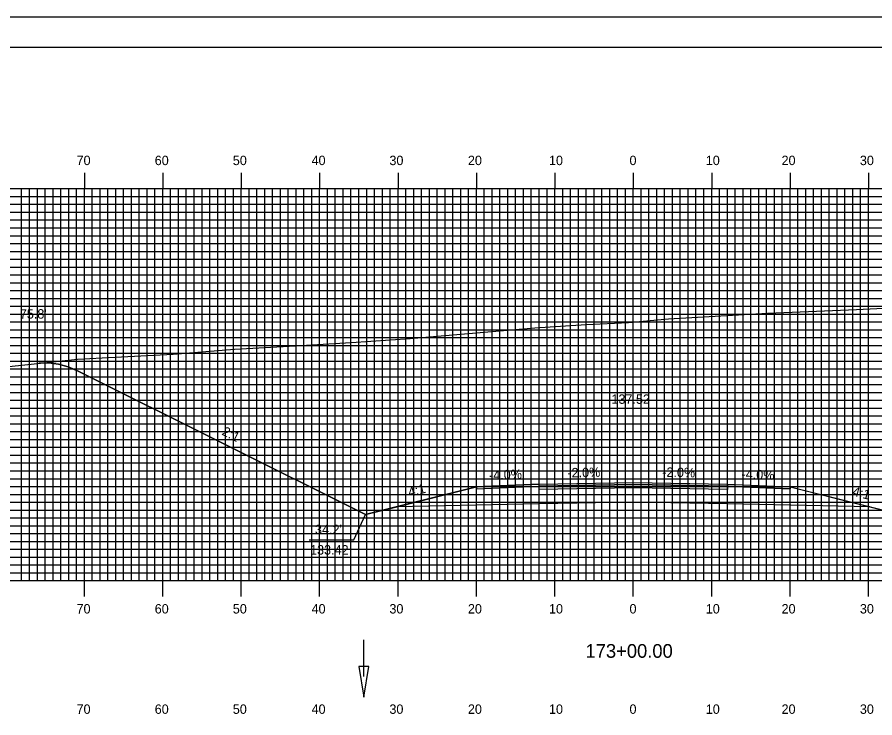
# Model space of a CAD drawing. Extents: x 1783041 to 1783384, y 442591 to 442811.
# Drawn here: x 1783127.9 to 1783237.3, y 442721.2 to 442810.5 of the extents above; entities that cross this region are included whole.
import ezdxf

# ---------------------------------------------------------------- set-up
doc = ezdxf.new("R2010")
doc.units = 0
for name, color, linetype in [('ANNOTATION', 7, 'Continuous'), ('BORDER', 7, 'Continuous'), ('D_Drainage_Ditch_Line', 7, 'Continuous'), ('D_Roadway_Centerline', 7, 'Continuous'), ('D_Roadway_Centerline_Text', 7, 'Continuous'), ('D_Roadway_Edge_Shoulder', 7, 'Continuous'), ('D_Roadway_Edge_TW', 7, 'Continuous'), ('D_Roadway_Pavement', 7, 'Continuous'), ('D_Roadway_SlopeLines', 7, 'Continuous'), ('D_Roadway_SubGrade', 7, 'Continuous'), ('D_Text_Standard', 7, 'Continuous'), ('H_V ANNOTATION', 7, 'Continuous'), ('MAJOR', 7, 'Continuous'), ('MINOR', 7, 'Continuous'), ('PLOT BOUNDARY', 7, 'Continuous'), ('S_Roadway_Centerline', 7, 'Continuous')]:
    doc.layers.add(name, color=color, linetype=linetype)

msp = doc.modelspace()

# ---------------------------------------------------------------- linework, layer by layer
at = {"layer": 'ANNOTATION'}
msp.add_lwpolyline([(1783165.13, 442743.86), (1783170.83, 442743.86), (1783172.29, 442747.09)], dxfattribs=at)
at = {"layer": 'BORDER'}
msp.add_lwpolyline([(1783056.86, 442596.67), (1783376.86, 442596.67), (1783376.86, 442806.67), (1783056.86, 442806.67)], close=True, dxfattribs=at)
at = {"layer": 'D_Drainage_Ditch_Line'}
msp.add_line((1783172.09, 442726.42), (1783172.09, 442731.12), dxfattribs=at)
msp.add_lwpolyline([(1783172.75, 442727.73), (1783171.44, 442727.73), (1783172.09, 442723.8)], close=True, dxfattribs=at)
at = {"layer": 'D_Roadway_Centerline'}
msp.add_lwpolyline([(1783130.65, 442766.39), (1783131.9, 442766.43), (1783133.15, 442766.28), (1783134.4, 442765.93), (1783135.65, 442765.4), (1783172.29, 442747.09), (1783176.29, 442748.09), (1783186.46, 442750.63), (1783194.46, 442750.95), (1783206.46, 442751.19), (1783218.46, 442750.95), (1783226.46, 442750.63), (1783236.63, 442748.09), (1783243.2, 442746.45), (1783302.51, 442776.1), (1783303.76, 442776.66), (1783305.01, 442777.08), (1783306.26, 442777.35), (1783307.51, 442777.49)], dxfattribs=at)
at = {"layer": 'D_Roadway_Edge_Shoulder'}
for points in [[(1783194.46, 442750.95), (1783186.46, 442750.63), (1783186.46, 442750.38), (1783194.46, 442750.7)], [(1783218.46, 442750.95), (1783226.46, 442750.63), (1783226.46, 442750.38), (1783218.46, 442750.7)]]:
    msp.add_lwpolyline(points, close=True, dxfattribs=at)
at = {"layer": 'D_Roadway_Edge_TW'}
msp.add_lwpolyline([(1783194.46, 442750.7), (1783194.46, 442750.95), (1783206.46, 442751.19), (1783218.46, 442750.95), (1783218.46, 442750.7), (1783206.46, 442750.94)], close=True, dxfattribs=at)
at = {"layer": 'D_Roadway_Pavement'}
msp.add_lwpolyline([(1783194.46, 442750.28), (1783194.46, 442750.7), (1783206.46, 442750.94), (1783218.46, 442750.7), (1783218.46, 442750.28), (1783206.46, 442750.52)], close=True, dxfattribs=at)
at = {"layer": 'D_Roadway_SlopeLines'}
for points in [[(1783172.29, 442747.09), (1783135.65, 442765.4), (1783134.4, 442765.93), (1783133.15, 442766.28), (1783131.9, 442766.43), (1783130.65, 442766.39)], [(1783186.46, 442750.63), (1783172.29, 442747.09)], [(1783226.46, 442750.63), (1783243.2, 442746.45)]]:
    msp.add_lwpolyline(points, dxfattribs=at)
at = {"layer": 'D_Roadway_SubGrade'}
msp.add_lwpolyline([(1783194.46, 442748.45), (1783176.29, 442748.09), (1783186.46, 442750.63), (1783186.46, 442750.38), (1783194.46, 442750.7), (1783206.46, 442750.94), (1783218.46, 442750.7), (1783226.46, 442750.38), (1783226.46, 442750.63), (1783236.63, 442748.09), (1783218.46, 442748.45), (1783206.46, 442748.69)], close=True, dxfattribs=at)
at = {"layer": 'MAJOR'}
for p, q in [((1783136.46, 442790.67), (1783136.46, 442788.67)), ((1783146.46, 442790.67), (1783146.46, 442788.67)), ((1783156.46, 442790.67), (1783156.46, 442788.67)), ((1783166.46, 442790.67), (1783166.46, 442788.67)), ((1783176.46, 442790.67), (1783176.46, 442788.67)), ((1783186.46, 442790.67), (1783186.46, 442788.67)), ((1783196.46, 442790.67), (1783196.46, 442788.67)), ((1783206.46, 442790.67), (1783206.46, 442788.67)), ((1783216.46, 442790.67), (1783216.46, 442788.67)), ((1783226.46, 442790.67), (1783226.46, 442788.67)), ((1783236.46, 442790.67), (1783236.46, 442788.67)), ((1783066.46, 442788.67), (1783346.46, 442788.67)), ((1783066.46, 442788.67), (1783346.46, 442788.67)), ((1783136.46, 442738.67), (1783136.46, 442788.67)), ((1783146.46, 442738.67), (1783146.46, 442788.67)), ((1783156.46, 442738.67), (1783156.46, 442788.67)), ((1783166.46, 442738.67), (1783166.46, 442788.67)), ((1783176.46, 442738.67), (1783176.46, 442788.67)), ((1783186.46, 442738.67), (1783186.46, 442788.67)), ((1783196.46, 442738.67), (1783196.46, 442788.67)), ((1783206.46, 442738.67), (1783206.46, 442788.67)), ((1783216.46, 442738.67), (1783216.46, 442788.67)), ((1783226.46, 442738.67), (1783226.46, 442788.67)), ((1783236.46, 442738.67), (1783236.46, 442788.67)), ((1783066.46, 442783.67), (1783346.46, 442783.67)), ((1783066.46, 442778.67), (1783346.46, 442778.67)), ((1783066.46, 442773.67), (1783346.46, 442773.67)), ((1783066.46, 442768.67), (1783346.46, 442768.67)), ((1783066.46, 442763.67), (1783346.46, 442763.67)), ((1783066.46, 442758.67), (1783346.46, 442758.67)), ((1783066.46, 442753.67), (1783346.46, 442753.67)), ((1783066.46, 442748.67), (1783346.46, 442748.67)), ((1783066.46, 442743.67), (1783346.46, 442743.67)), ((1783066.46, 442738.67), (1783346.46, 442738.67)), ((1783066.46, 442738.67), (1783346.46, 442738.67)), ((1783136.46, 442736.66), (1783136.46, 442738.67)), ((1783146.46, 442736.66), (1783146.46, 442738.67)), ((1783156.46, 442736.66), (1783156.46, 442738.67)), ((1783166.46, 442736.66), (1783166.46, 442738.67)), ((1783176.46, 442736.66), (1783176.46, 442738.67)), ((1783186.46, 442736.66), (1783186.46, 442738.67)), ((1783196.46, 442736.66), (1783196.46, 442738.67)), ((1783206.46, 442736.66), (1783206.46, 442738.67)), ((1783216.46, 442736.66), (1783216.46, 442738.67)), ((1783226.46, 442736.66), (1783226.46, 442738.67)), ((1783236.46, 442736.66), (1783236.46, 442738.67))]:
    msp.add_line(p, q, dxfattribs=at)
at = {"layer": 'MINOR'}
for p, q in [((1783128.46, 442738.67), (1783128.46, 442788.67)), ((1783129.46, 442738.67), (1783129.46, 442788.67)), ((1783130.46, 442738.67), (1783130.46, 442788.67)), ((1783131.46, 442738.67), (1783131.46, 442788.67)), ((1783132.46, 442738.67), (1783132.46, 442788.67)), ((1783133.46, 442738.67), (1783133.46, 442788.67)), ((1783134.46, 442738.67), (1783134.46, 442788.67)), ((1783135.46, 442738.67), (1783135.46, 442788.67)), ((1783137.46, 442738.67), (1783137.46, 442788.67)), ((1783138.46, 442738.67), (1783138.46, 442788.67)), ((1783139.46, 442738.67), (1783139.46, 442788.67)), ((1783140.46, 442738.67), (1783140.46, 442788.67)), ((1783141.46, 442738.67), (1783141.46, 442788.67)), ((1783142.46, 442738.67), (1783142.46, 442788.67)), ((1783143.46, 442738.67), (1783143.46, 442788.67)), ((1783144.46, 442738.67), (1783144.46, 442788.67)), ((1783145.46, 442738.67), (1783145.46, 442788.67)), ((1783147.46, 442738.67), (1783147.46, 442788.67)), ((1783148.46, 442738.67), (1783148.46, 442788.67)), ((1783149.46, 442738.67), (1783149.46, 442788.67)), ((1783150.46, 442738.67), (1783150.46, 442788.67)), ((1783151.46, 442738.67), (1783151.46, 442788.67)), ((1783152.46, 442738.67), (1783152.46, 442788.67)), ((1783153.46, 442738.67), (1783153.46, 442788.67)), ((1783154.46, 442738.67), (1783154.46, 442788.67)), ((1783155.46, 442738.67), (1783155.46, 442788.67)), ((1783157.46, 442738.67), (1783157.46, 442788.67)), ((1783158.46, 442738.67), (1783158.46, 442788.67)), ((1783159.46, 442738.67), (1783159.46, 442788.67)), ((1783160.46, 442738.67), (1783160.46, 442788.67)), ((1783161.46, 442738.67), (1783161.46, 442788.67)), ((1783162.46, 442738.67), (1783162.46, 442788.67)), ((1783163.46, 442738.67), (1783163.46, 442788.67)), ((1783164.46, 442738.67), (1783164.46, 442788.67)), ((1783165.46, 442738.67), (1783165.46, 442788.67)), ((1783167.46, 442738.67), (1783167.46, 442788.67)), ((1783168.46, 442738.67), (1783168.46, 442788.67)), ((1783169.46, 442738.67), (1783169.46, 442788.67)), ((1783170.46, 442738.67), (1783170.46, 442788.67)), ((1783171.46, 442738.67), (1783171.46, 442788.67)), ((1783172.46, 442738.67), (1783172.46, 442788.67)), ((1783173.46, 442738.67), (1783173.46, 442788.67)), ((1783174.46, 442738.67), (1783174.46, 442788.67)), ((1783175.46, 442738.67), (1783175.46, 442788.67)), ((1783177.46, 442738.67), (1783177.46, 442788.67)), ((1783178.46, 442738.67), (1783178.46, 442788.67)), ((1783179.46, 442738.67), (1783179.46, 442788.67)), ((1783180.46, 442738.67), (1783180.46, 442788.67)), ((1783181.46, 442738.67), (1783181.46, 442788.67)), ((1783182.46, 442738.67), (1783182.46, 442788.67)), ((1783183.46, 442738.67), (1783183.46, 442788.67)), ((1783184.46, 442738.67), (1783184.46, 442788.67)), ((1783185.46, 442738.67), (1783185.46, 442788.67)), ((1783187.46, 442738.67), (1783187.46, 442788.67)), ((1783188.46, 442738.67), (1783188.46, 442788.67)), ((1783189.46, 442738.67), (1783189.46, 442788.67)), ((1783190.46, 442738.67), (1783190.46, 442788.67)), ((1783191.46, 442738.67), (1783191.46, 442788.67)), ((1783192.46, 442738.67), (1783192.46, 442788.67)), ((1783193.46, 442738.67), (1783193.46, 442788.67)), ((1783194.46, 442738.67), (1783194.46, 442788.67)), ((1783195.46, 442738.67), (1783195.46, 442788.67)), ((1783197.46, 442738.67), (1783197.46, 442788.67)), ((1783198.46, 442738.67), (1783198.46, 442788.67)), ((1783199.46, 442738.67), (1783199.46, 442788.67)), ((1783200.46, 442738.67), (1783200.46, 442788.67)), ((1783201.46, 442738.67), (1783201.46, 442788.67)), ((1783202.46, 442738.67), (1783202.46, 442788.67)), ((1783203.46, 442738.67), (1783203.46, 442788.67)), ((1783204.46, 442738.67), (1783204.46, 442788.67)), ((1783205.46, 442738.67), (1783205.46, 442788.67)), ((1783207.46, 442738.67), (1783207.46, 442788.67)), ((1783208.46, 442738.67), (1783208.46, 442788.67)), ((1783209.46, 442738.67), (1783209.46, 442788.67)), ((1783210.46, 442738.67), (1783210.46, 442788.67)), ((1783211.46, 442738.67), (1783211.46, 442788.67)), ((1783212.46, 442738.67), (1783212.46, 442788.67)), ((1783213.46, 442738.67), (1783213.46, 442788.67)), ((1783214.46, 442738.67), (1783214.46, 442788.67)), ((1783215.46, 442738.67), (1783215.46, 442788.67)), ((1783217.46, 442738.67), (1783217.46, 442788.67)), ((1783218.46, 442738.67), (1783218.46, 442788.67)), ((1783219.46, 442738.67), (1783219.46, 442788.67)), ((1783220.46, 442738.67), (1783220.46, 442788.67)), ((1783221.46, 442738.67), (1783221.46, 442788.67)), ((1783222.46, 442738.67), (1783222.46, 442788.67)), ((1783223.46, 442738.67), (1783223.46, 442788.67)), ((1783224.46, 442738.67), (1783224.46, 442788.67)), ((1783225.46, 442738.67), (1783225.46, 442788.67)), ((1783227.46, 442738.67), (1783227.46, 442788.67)), ((1783228.46, 442738.67), (1783228.46, 442788.67)), ((1783229.46, 442738.67), (1783229.46, 442788.67)), ((1783230.46, 442738.67), (1783230.46, 442788.67)), ((1783231.46, 442738.67), (1783231.46, 442788.67)), ((1783232.46, 442738.67), (1783232.46, 442788.67)), ((1783233.46, 442738.67), (1783233.46, 442788.67)), ((1783234.46, 442738.67), (1783234.46, 442788.67)), ((1783235.46, 442738.67), (1783235.46, 442788.67)), ((1783066.46, 442787.67), (1783346.46, 442787.67)), ((1783066.46, 442786.67), (1783346.46, 442786.67)), ((1783066.46, 442785.67), (1783346.46, 442785.67)), ((1783066.46, 442784.67), (1783346.46, 442784.67)), ((1783066.46, 442782.67), (1783346.46, 442782.67)), ((1783066.46, 442781.67), (1783346.46, 442781.67)), ((1783066.46, 442780.67), (1783346.46, 442780.67)), ((1783066.46, 442779.67), (1783346.46, 442779.67)), ((1783066.46, 442777.67), (1783346.46, 442777.67)), ((1783066.46, 442776.67), (1783346.46, 442776.67)), ((1783066.46, 442775.67), (1783346.46, 442775.67)), ((1783066.46, 442774.67), (1783346.46, 442774.67)), ((1783066.46, 442772.67), (1783346.46, 442772.67)), ((1783066.46, 442771.67), (1783346.46, 442771.67)), ((1783066.46, 442770.67), (1783346.46, 442770.67)), ((1783066.46, 442769.67), (1783346.46, 442769.67)), ((1783066.46, 442767.67), (1783346.46, 442767.67)), ((1783066.46, 442766.67), (1783346.46, 442766.67)), ((1783066.46, 442765.67), (1783346.46, 442765.67)), ((1783066.46, 442764.67), (1783346.46, 442764.67)), ((1783066.46, 442762.67), (1783346.46, 442762.67)), ((1783066.46, 442761.67), (1783346.46, 442761.67)), ((1783066.46, 442760.67), (1783346.46, 442760.67)), ((1783066.46, 442759.67), (1783346.46, 442759.67)), ((1783066.46, 442757.67), (1783346.46, 442757.67)), ((1783066.46, 442756.67), (1783346.46, 442756.67)), ((1783066.46, 442755.67), (1783346.46, 442755.67)), ((1783066.46, 442754.67), (1783346.46, 442754.67)), ((1783066.46, 442752.67), (1783346.46, 442752.67)), ((1783066.46, 442751.67), (1783346.46, 442751.67)), ((1783066.46, 442750.67), (1783346.46, 442750.67)), ((1783066.46, 442749.67), (1783346.46, 442749.67)), ((1783066.46, 442747.67), (1783346.46, 442747.67)), ((1783066.46, 442746.67), (1783346.46, 442746.67)), ((1783066.46, 442745.67), (1783346.46, 442745.67)), ((1783066.46, 442744.67), (1783346.46, 442744.67)), ((1783066.46, 442742.67), (1783346.46, 442742.67)), ((1783066.46, 442741.67), (1783346.46, 442741.67)), ((1783066.46, 442740.67), (1783346.46, 442740.67)), ((1783066.46, 442739.67), (1783346.46, 442739.67))]:
    msp.add_line(p, q, dxfattribs=at)
at = {"layer": 'PLOT BOUNDARY'}
msp.add_lwpolyline([(1783040.67, 442590.55), (1783380.67, 442590.55), (1783380.67, 442810.55), (1783040.67, 442810.55)], close=True, dxfattribs=at)
at = {"layer": 'S_Roadway_Centerline'}
msp.add_lwpolyline([(1783124.39, 442765.72), (1783132.85, 442766.62), (1783135.59, 442766.9), (1783138.72, 442767.09), (1783147.78, 442767.56), (1783155.62, 442768.18), (1783163.35, 442768.62), (1783170.5, 442769.04), (1783178.02, 442769.56), (1783186.93, 442770.32), (1783193.92, 442770.9), (1783200.46, 442771.34), (1783205.85, 442771.61), (1783210.97, 442772.05), (1783223.59, 442772.78), (1783228.81, 442773), (1783234.92, 442773.24), (1783241.03, 442773.57)], dxfattribs=at)

# ---------------------------------------------------------------- texts
at = {"layer": 'ANNOTATION'}
for s, rotation, p in [('2:1', 333.4349, (1783153.9, 442757.31)), ('-4.0%', 2.2906, (1783188.09, 442751.5)), ('-2.0%', 1.1458, (1783198.07, 442751.82)), ('-2.0%', 358.8542, (1783210.15, 442751.92)), ('-4.0%', 357.7094, (1783220.25, 442751.68)), ('4:1', 14.0362, (1783177.91, 442749.35)), ('4:1', 345.9638, (1783234.34, 442749.52))]:
    msp.add_text(s, height=1.2, rotation=rotation, dxfattribs=at).set_placement(p)
for s, p in [("34.2'", (1783165.87, 442744.59)), ('133.42', (1783165.24, 442741.99))]:
    msp.add_text(s, height=1.2, dxfattribs=at).set_placement(p)
at = {"layer": 'D_Roadway_Centerline'}
for s, p in [('C', (1783206.45, 442751.19)), ('L', (1783206.46, 442751.18))]:
    msp.add_text(s, height=0.0146, dxfattribs=at).set_placement(p)
at = {"layer": 'D_Roadway_Centerline_Text'}
msp.add_text('137.52', height=1.2, dxfattribs=at).set_placement((1783203.68, 442761.22))
at = {"layer": 'D_Text_Standard'}
msp.add_text("75.8'", height=1.2, dxfattribs=at).set_placement((1783128.23, 442772.09))
at = {"layer": 'H_V ANNOTATION'}
for s, height, p in [('70', 1.2, (1783135.46, 442791.67)), ('60', 1.2, (1783145.43, 442791.67)), ('50', 1.2, (1783155.39, 442791.67)), ('40', 1.2, (1783165.43, 442791.67)), ('30', 1.2, (1783175.36, 442791.67)), ('20', 1.2, (1783185.37, 442791.67)), ('10', 1.2, (1783195.71, 442791.67)), ('0', 1.2, (1783205.98, 442791.67)), ('10', 1.2, (1783215.71, 442791.67)), ('20', 1.2, (1783225.37, 442791.67)), ('30', 1.2, (1783235.36, 442791.67)), ('70', 1.2, (1783135.46, 442734.47)), ('60', 1.2, (1783145.43, 442734.47)), ('50', 1.2, (1783155.39, 442734.47)), ('40', 1.2, (1783165.43, 442734.47)), ('30', 1.2, (1783175.36, 442734.47)), ('20', 1.2, (1783185.37, 442734.47)), ('10', 1.2, (1783195.71, 442734.47)), ('0', 1.2, (1783205.98, 442734.47)), ('10', 1.2, (1783215.71, 442734.47)), ('20', 1.2, (1783225.37, 442734.47)), ('30', 1.2, (1783235.36, 442734.47)), ('173+00.00', 1.75, (1783200.37, 442728.82)), ('70', 1.2, (1783135.46, 442721.67)), ('60', 1.2, (1783145.43, 442721.67)), ('50', 1.2, (1783155.39, 442721.67)), ('40', 1.2, (1783165.43, 442721.67)), ('30', 1.2, (1783175.36, 442721.67)), ('20', 1.2, (1783185.37, 442721.67)), ('10', 1.2, (1783195.71, 442721.67)), ('0', 1.2, (1783205.98, 442721.67)), ('10', 1.2, (1783215.71, 442721.67)), ('20', 1.2, (1783225.37, 442721.67)), ('30', 1.2, (1783235.36, 442721.67))]:
    msp.add_text(s, height=height, dxfattribs=at).set_placement(p)

doc.saveas('drawing.dxf')
